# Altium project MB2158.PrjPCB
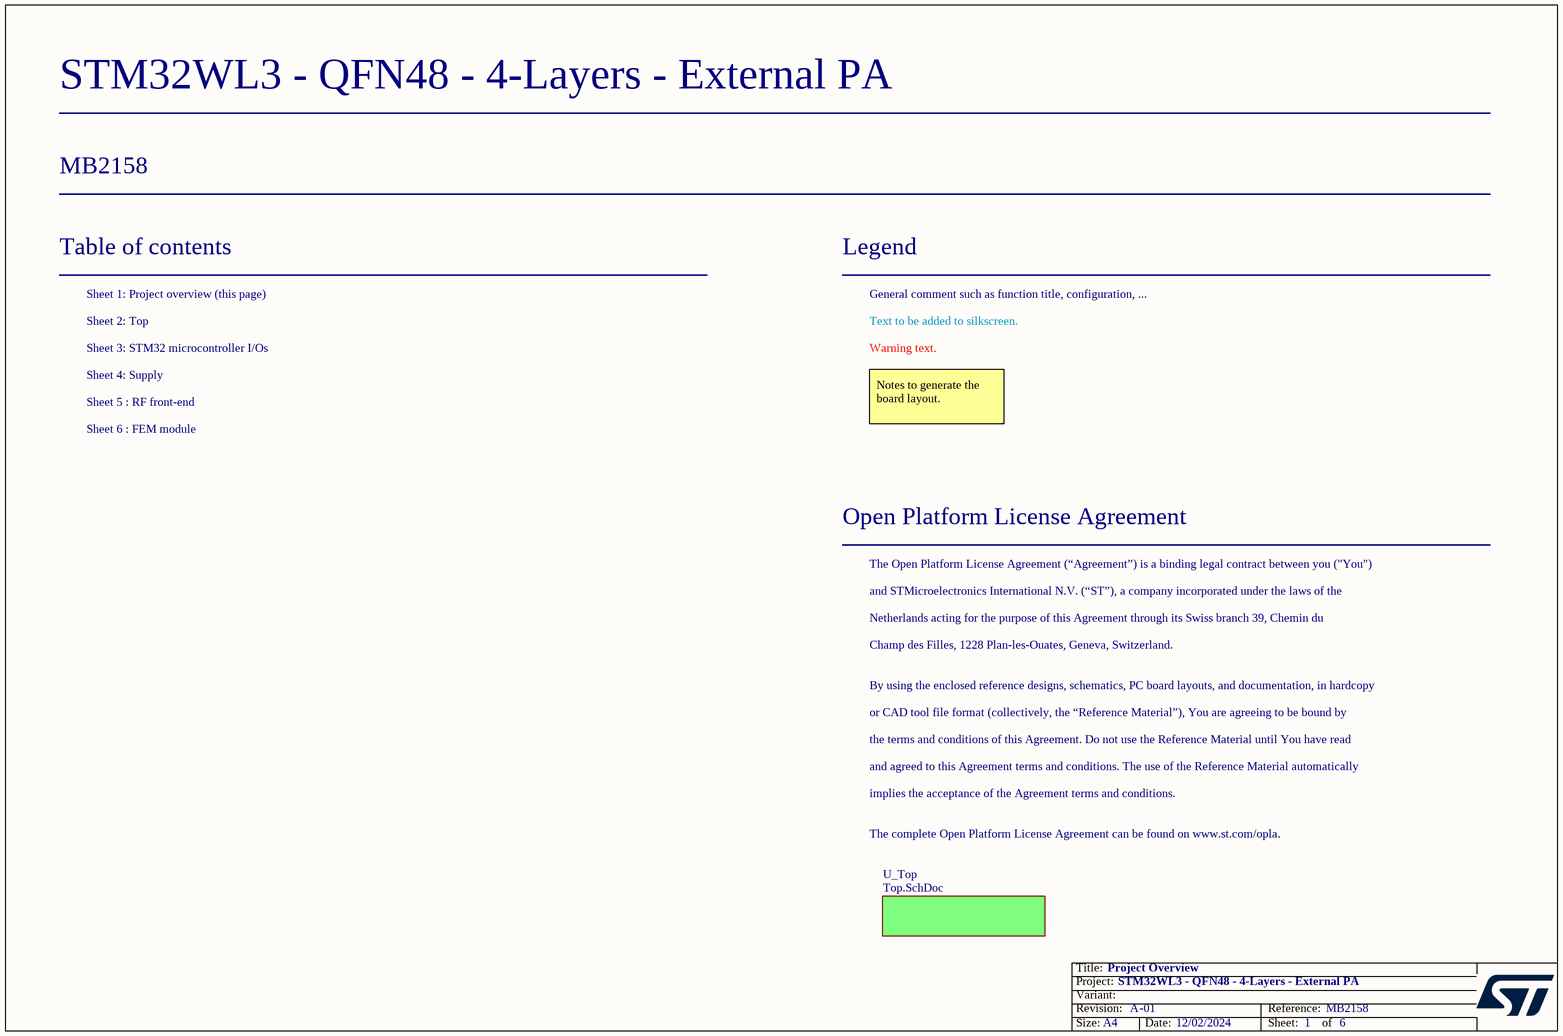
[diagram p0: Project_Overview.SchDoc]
Board_Assembly_Revision: 01; Board_Document_Date: 12/02/2024; Board_Name: STM32WL3 - QFN48 - 4-Layers - External PA; Board_PCB_Revision: A; Board_Reference: MB2158
6 sheets, 108 parts. Net scope: flat (ports and power ports of the same name join across sheets).
Board file: MB2158.PcbDoc
Sheets:
  Project_Overview.SchDoc
    U_Top = Top.SchDoc
      Designator = MCU_IOs.SchDoc
      Designator = RF.SchDoc
      Designator = Supply.SchDoc
      U_FEM = FEM.SchDoc

## Sheet Project_Overview.SchDoc: Project Overview
size A4; Date: Not used; ApprovedBy: Not used; CheckedBy: Not used; Author: Not used; CompanyName: STMicroelectronics; DrawnBy: Not used; Engineer: Not used; Organization: Not used; Address1: Not used; Address2: Not used; Address3: Not used; Address4: Not used; DocumentNumber: Not used; Revision: Not used; SheetNumber: 1; SheetTotal: 6

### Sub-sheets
U_Top = Top.SchDoc: no entries

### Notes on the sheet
- Table of contents
- Sheet 1: Project overview (this page)
- Legend
- General comment such as function title, configuration, ...
- Sheet 2: Top
- Sheet 3: STM32 microcontroller I/Os
- Sheet 4: Supply
- Text to be added to silkscreen.
- Warning text.
- Sheet 5 : RF front-end
- Sheet 6 : FEM module
- Notes to generate the board layout.
- Open Platform License Agreement
- The Open Platform License Agreement (“Agreement”) is a binding legal contract between you ("You")
- and STMicroelectronics International N.V. (“ST”), a company incorporated under the laws of the
- Netherlands acting for the purpose of this Agreement through its Swiss branch 39, Chemin du
- Champ des Filles, 1228 Plan-les-Ouates, Geneva, Switzerland.
- By using the enclosed reference designs, schematics, PC board layouts, and documentation, in hardcopy
- or CAD tool file format (collectively, the “Reference Material”), You are agreeing to be bound by
- the terms and conditions of this Agreement. Do not use the Reference Material until You have read
- and agreed to this Agreement terms and conditions. The use of the Reference Material automatically
- implies the acceptance of the Agreement terms and conditions.
- The complete Open Platform License Agreement can be found on www.st.com/opla.

## Sheet Top.SchDoc: Top Schematic
size A4; Date: Not used; ApprovedBy: Not used; CheckedBy: Not used; Author: Not used; CompanyName: STMicroelectronics; DrawnBy: Not used; Engineer: Not used; Organization: Not used; Address1: Not used; Address2: Not used; Address3: Not used; Address4: Not used; DocumentNumber: Not used; Revision: Not used; SheetNumber: 2; SheetTotal: 6
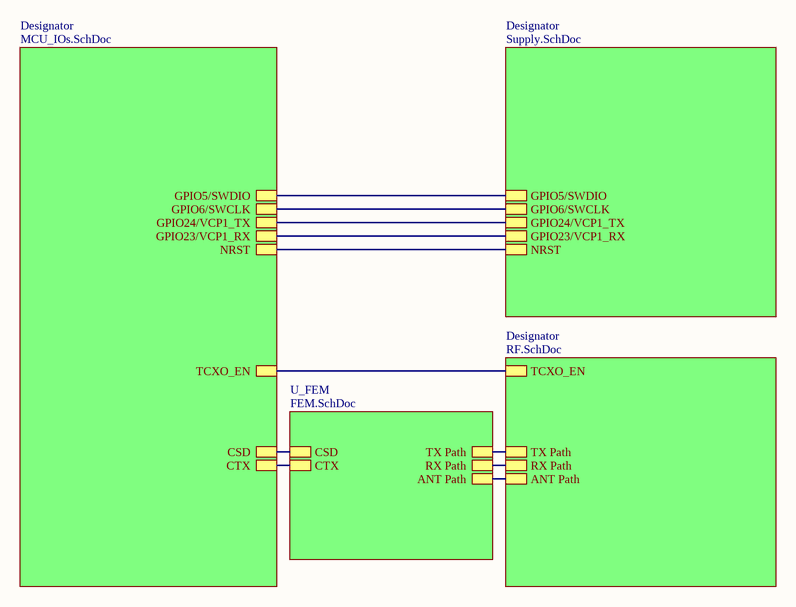
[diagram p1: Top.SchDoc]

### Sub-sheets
Designator = MCU_IOs.SchDoc: NRST, GPIO5/SWDIO, GPIO6/SWCLK, GPIO24/VCP1_TX, GPIO23/VCP1_RX, CTX, CSD, TCXO_EN
Designator = RF.SchDoc: RX Path, TX Path, ANT Path, TCXO_EN
Designator = Supply.SchDoc: NRST, GPIO5/SWDIO, GPIO6/SWCLK, GPIO23/VCP1_RX, GPIO24/VCP1_TX
U_FEM = FEM.SchDoc: TX Path, RX Path, CSD, CTX, ANT Path

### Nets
(unnamed): sheet Designator/NRST, sheet Designator/NRST
(unnamed): sheet Designator/GPIO5/SWDIO, sheet Designator/GPIO5/SWDIO  [a separate net that carries the same name]
(unnamed): sheet Designator/GPIO6/SWCLK, sheet Designator/GPIO6/SWCLK  [a separate net that carries the same name]
(unnamed): sheet Designator/GPIO24/VCP1_TX, sheet Designator/GPIO24/VCP1_TX  [a separate net that carries the same name]
(unnamed): sheet Designator/GPIO23/VCP1_RX, sheet Designator/GPIO23/VCP1_RX  [a separate net that carries the same name]
(unnamed): sheet Designator/CTX, sheet U_FEM/CTX  [a separate net that carries the same name]
(unnamed): sheet Designator/CSD, sheet U_FEM/CSD  [a separate net that carries the same name]
(unnamed): sheet Designator/TCXO_EN, sheet Designator/TCXO_EN  [a separate net that carries the same name]
(unnamed): sheet Designator/RX Path, sheet U_FEM/RX Path  [a separate net that carries the same name]
(unnamed): sheet Designator/TX Path, sheet U_FEM/TX Path  [a separate net that carries the same name]
(unnamed): sheet Designator/ANT Path, sheet U_FEM/ANT Path  [a separate net that carries the same name]

## Sheet MCU_IOs.SchDoc: STM32 I/Os & Clock
size A4; Date: Not used; ApprovedBy: Not used; CheckedBy: Not used; Author: Not used; CompanyName: STMicroelectronics; DrawnBy: Not used; Engineer: Not used; Organization: Not used; Address1: Not used; Address2: Not used; Address3: Not used; Address4: Not used; DocumentNumber: Not used; Revision: Not used; SheetNumber: 3; SheetTotal: 6
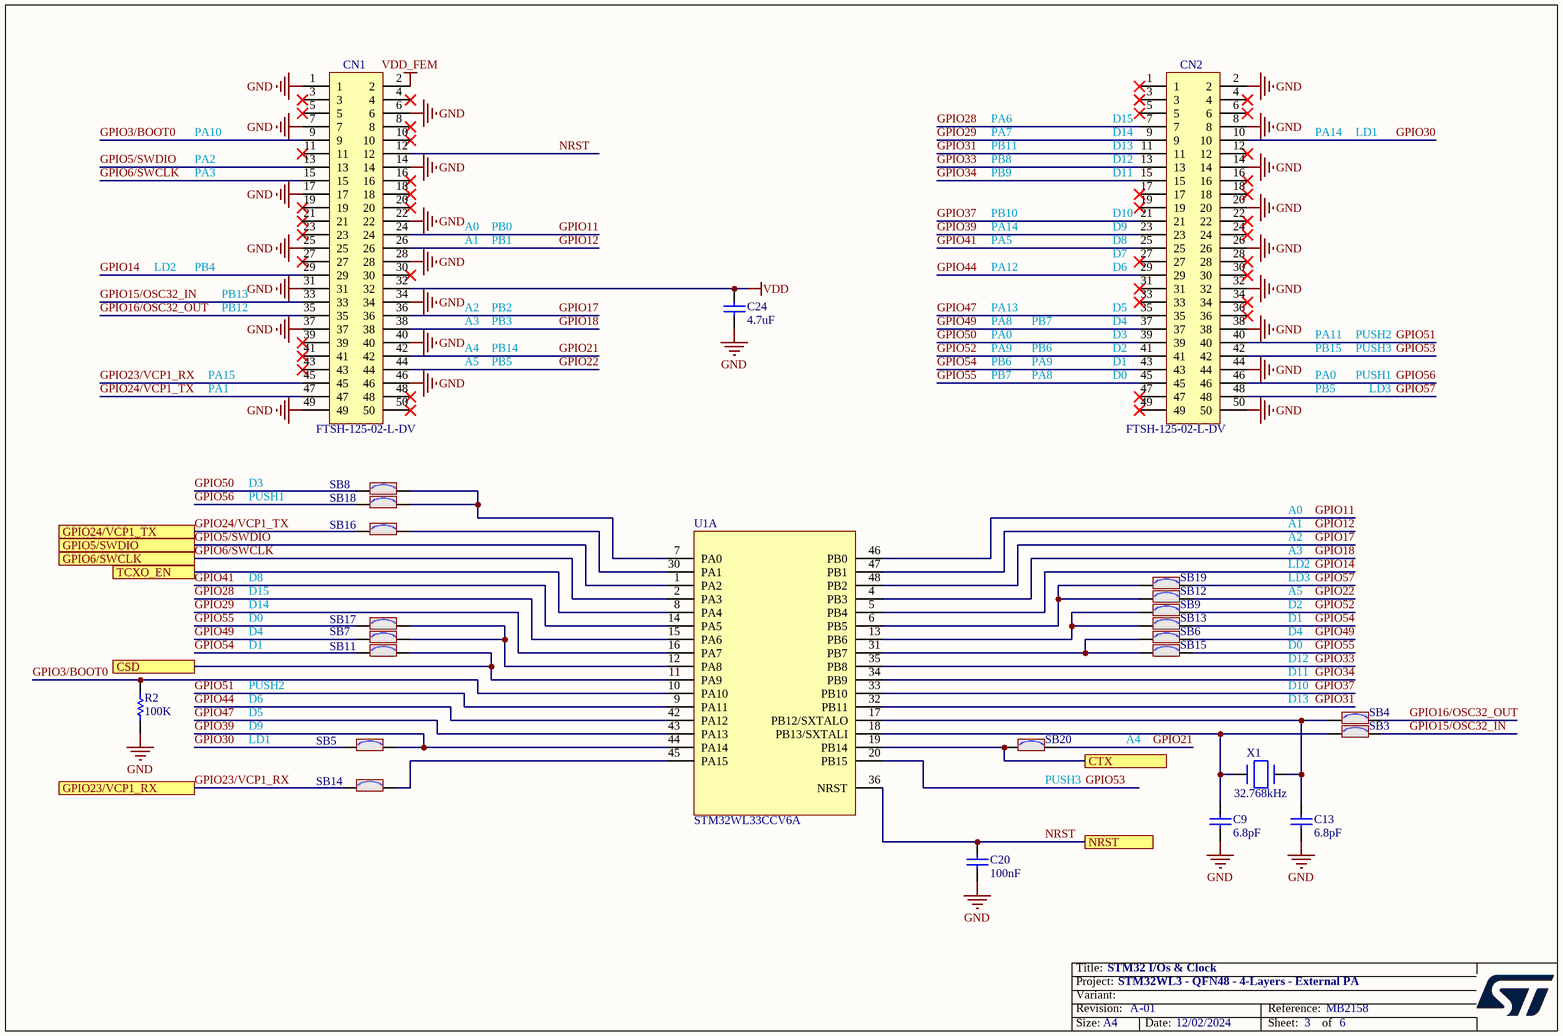
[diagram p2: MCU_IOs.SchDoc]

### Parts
C9  value 6.8pF  [C0402]  (hidden comment: Capacitor)
C13  value 6.8pF  [C0402]  (hidden comment: Capacitor)
C20  value 100nF  [C0402]  (hidden comment: Capacitor)
C24  value 4.7uF  [C0402]  (hidden comment: Capacitor)
CN1  FTSH-125-02-L-DV  [CON_SAMTEC_FTSH-125-02-L-DV]
CN2  FTSH-125-02-L-DV  [CON_SAMTEC_FTSH-125-02-L-DV]
R2  value 100K  [R0402]  (hidden comment: Resistor)
SB3  SB_ON  [SOLDER-BRIDGE_R0402-0R]  (value not drawn)
SB4  SB_ON  [SOLDER-BRIDGE_R0402-0R]  (value not drawn)
SB5  SB_ON  [SOLDER-BRIDGE_R0402-0R]  (value not drawn)
SB6  SB_ON  [SOLDER-BRIDGE_R0402-0R]  (value not drawn)
SB7  SB_ON  [SOLDER-BRIDGE_R0402-0R]  (value not drawn)
SB8  SB_ON  [SOLDER-BRIDGE_R0402-0R]  (value not drawn)
SB9  SB_ON  [SOLDER-BRIDGE_R0402-0R]  (value not drawn)
SB11  SB_ON  [SOLDER-BRIDGE_R0402-0R]  (value not drawn)
SB12  SB_ON  [SOLDER-BRIDGE_R0402-0R]  (value not drawn)
SB13  SB_ON  [SOLDER-BRIDGE_R0402-0R]  (value not drawn)
SB14  SB_ON  [SOLDER-BRIDGE_R0402-0R]  (value not drawn)
SB15  SB_ON  [SOLDER-BRIDGE_R0402-0R]  (value not drawn)
SB16  SB_ON  [SOLDER-BRIDGE_R0402-0R]  (value not drawn)
SB17  SB_ON  [SOLDER-BRIDGE_R0402-0R]  (value not drawn)
SB18  SB_ON  [SOLDER-BRIDGE_R0402-0R]  (value not drawn)
SB19  SB_ON  [SOLDER-BRIDGE_R0402-0R]  (value not drawn)
SB20  SB_ON  [SOLDER-BRIDGE_R0402-0R]  (value not drawn)
U1  value STM32WL33CCV6A  [ICC_QFN48-EPAD-4P5X4P5_6X6_P040]  (hidden comment: STM32WL33)  (part A of 3)
X1  value 32.768kHz  [CRY_NX2012SA_2P]  (hidden comment: XTAL_2_PINS)

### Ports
CSD, CTX, GPIO5/SWDIO, GPIO6/SWCLK, GPIO23/VCP1_RX, GPIO24/VCP1_TX, NRST, TCXO_EN

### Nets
GND: C9.1 C13.1 C20.1 C24.1 CN1.1 CN1.6 CN1.7 CN1.14 CN1.17 CN1.22 CN1.25 CN1.28 CN1.31 CN1.34 CN1.37 CN1.40 CN1.46 CN1.49 CN2.2 CN2.8 CN2.14 CN2.20 CN2.26 CN2.32 CN2.38 CN2.44 CN2.50 R2.1
VDD: C24.2 CN1.32
VDD_FEM: CN1.2
CSD: SB11.2 U1.11(PA9) ; port CSD
CTX: SB20.1 U1.19(PB14) ; port CTX
GPIO3/BOOT0: CN1.9 R2.2 U1.10(PA10)
GPIO5/SWDIO: CN1.13 U1.1(PA2) ; port GPIO5/SWDIO
GPIO6/SWCLK: CN1.15 U1.2(PA3) ; port GPIO6/SWCLK
GPIO11: CN1.24 U1.46(PB0)
GPIO12: CN1.26 U1.47(PB1)
GPIO14: CN1.29 U1.5(PB4)
GPIO15/OSC32_IN: CN1.33 SB3.2
GPIO16/OSC32_OUT: CN1.35 SB4.2
GPIO17: CN1.36 U1.48(PB2)
GPIO18: CN1.38 U1.4(PB3)
GPIO21: CN1.42 SB20.2
GPIO22: CN1.44 SB12.2
GPIO23/VCP1_RX: CN1.45 SB14.1 ; port GPIO23/VCP1_RX
GPIO24/VCP1_TX: CN1.47 SB16.1 ; port GPIO24/VCP1_TX
GPIO28: CN2.7 U1.15(PA6)
GPIO29: CN2.9 U1.16(PA7)
GPIO30: CN2.10 SB5.1
GPIO31: CN2.11 U1.32(PB11)
GPIO33: CN2.13 U1.35(PB8)
GPIO34: CN2.15 U1.34(PB9)
GPIO37: CN2.21 U1.33(PB10)
GPIO39: CN2.23 SB5.2 U1.44(PA14)
GPIO41: CN2.25 U1.14(PA5)
GPIO44: CN2.29 U1.42(PA12)
GPIO47: CN2.35 U1.43(PA13)
GPIO49: CN2.37 SB6.2 SB7.1
GPIO50: CN2.39 SB8.1
GPIO51: CN2.40 U1.9(PA11)
GPIO52: CN2.41 SB9.2
GPIO53: CN2.42 U1.20(PB15)
GPIO54: CN2.43 SB11.1 SB13.2
GPIO55: CN2.45 SB15.2 SB17.1
GPIO56: CN2.46 SB18.1
GPIO57: CN2.48 SB19.2
NRST: C20.2 CN1.12 U1.36(NRST) ; port NRST
TCXO_EN: U1.8(PA4) ; port TCXO_EN
NetC9_2: C9.2 SB3.1 U1.18(PB13/SXTALI) X1.2(X2)
NetC13_2: C13.2 SB4.1 U1.17(PB12/SXTALO) X1.1(X1)
NetSB6_1: SB6.1 SB15.1 U1.31(PB7)
NetSB7_2: SB7.2 SB17.2 U1.12(PA8)
NetSB8_2: SB8.2 SB18.2 U1.7(PA0)
NetSB9_1: SB9.1 SB13.1 U1.13(PB6)
NetSB12_1: SB12.1 SB19.1 U1.6(PB5)
NetSB14_2: SB14.2 U1.45(PA15)
NetSB16_2: SB16.2 U1.30(PA1)

Not connected (* = marked no-connect by the designer): CN1 3* 4* 5* 8* 10* 11* 16* 18* 19* 20* 21* 23* 27* 30* 39* 41* 43* 48* 50*; CN2 1* 3* 4* 5* 6* 12* 16* 17* 18* 19* 22* 24* 27* 28* 30* 31* 33* 34* 36* 47* 49*

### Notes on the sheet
- PA10
- PA2
- PA3
- PA7
- PA6
- PB8
- PB11
- PB9
- (near CN2) D11
- (near CN2) D13
- (near CN2) D14
- (near CN2) D15
- (near CN2) D12
- PA14
- LD1
- A0
- A1
- PB1
- PB0
- PA5
- PB10
- (near CN2) D10
- (near CN2) D9
- (near CN2) D8
- LD2
- PB4
- PB13
- PB12
- A2
- PB2
- PA13
- PA12
- (near CN2) D7
- (near CN2) D6
- (near CN2) D5
- PA15
- A5
- A4
- A3
- PB5
- PB14
- PB3
- PB7
- PB6
- PA0
- PA9
- PA8
- (near CN2) D1
- (near CN2) D4
- (near CN2) D3
- (near CN2) D2
- (near CN2) D0
- PA11
- PB15
- PUSH1
- PUSH2
- PUSH3
- PA1
- LD3
- D3
- D8
- D14
- D15
- D1
- D0
- D4
- D2
- D6
- D5
- D10
- D12
- D11
- D13
- D9
- (near SB20) PUSH3

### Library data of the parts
C9 C13 = MCD-03452: Capacitor, MLCC, 6.8pF, ±0.05pF, C0G, 50V, 0402, T=0.5mm; Part_Preference: Recommended; Manufacturer: MURATA; Manufacturer_Part_Number: GJM1555C1H6R8WB01; Order_Code_RS: NA; ShowFields: YES; ID: 5568
C20 = MCD-00006: Capacitor, MLCC, 100nF, 16V, X7R, +/-10%, 0402, T=0.5mm; Manufacturer_Part_Number: CC0402KRX7R7BB104; Manufacturer: YAGEO; Alternate_Manufacturer_Part_Number: GCM155R71C104KA55D; Alternate_Manufacturer: MURATA; Part_Preference: Recommended; Order_Code_RS: 616-9701
C24 = MCD-03431: Capacitor, MLCC, 4.7uF, X5R, 10 V, 0402, ± 20%, T=0.5mm; Part_Preference: Recommended; Manufacturer: MURATA; Manufacturer_Part_Number: GRM155R61A475MEAAD; Order_Code_RS: 172-6870; ShowFields: YES; ID: 5547
CN1 CN2 = MCD-02746: Header, 25x2, 12.7mm, VR, SMD, T=4.83mm; Part_Type: Connector; Part_Preference: Recommended; Manufacturer: SAMTEC; Value: Header 25x2; ShowFields: YES; ID: 4858; Component_Country_Of_Origin: China, Costa Rica, Malaysia, USA, Vietnam
R2 = MCD-03301: Resistor, 100K, 0402, +/-1%, 1/16W; Part_Preference: Alternate; Manufacturer: YAGEO; Manufacturer_Part_Number: RT0402FRE07100KL; Alternate_EMS: M; ShowFields: YES; ID: 5417
SB3-SB9 SB11-SB20 = MCD-01618: Solder Bridge 0402 ON; Part_Type: Misc; Part_Preference: Recommended; Manufacturer: YAGEO; Manufacturer_Part_Number: RC0402JR-070RL; Order_Code_RS: 618-5804; Component_Country_Of_Origin: China
U1 = MCD-03488: IC, Programmable Sub-1GHz wireless SoC; Part_Preference: Recommended; Manufacturer: STMICROELECTRONICS; Component_Country_Of_Origin: Unknown; ShowFields: YES; ID: 5604
X1 = MCD-01445: Crystal, 32.768kHz, 7pF, +/-20ppm, 80K, 2.05x1.2mm; BMS_Part_Number: 9157043; Part_Type: Crystal_Osc; Part_Preference: Recommended; Manufacturer: NDK; Manufacturer_Part_Number: NX2012SA-32.768KHZ-EXS00A-MU00389; Component_Country_Of_Origin: Unknown; ShowFields: YES; ID: 3545

## Sheet RF.SchDoc: STM32 RF
size A4; Date: Not used; ApprovedBy: Not used; CheckedBy: Not used; Author: Not used; CompanyName: STMicroelectronics; DrawnBy: Not used; Engineer: Not used; Organization: Not used; Address1: Not used; Address2: Not used; Address3: Not used; Address4: Not used; DocumentNumber: Not used; Revision: Not used; SheetNumber: 5; SheetTotal: 6
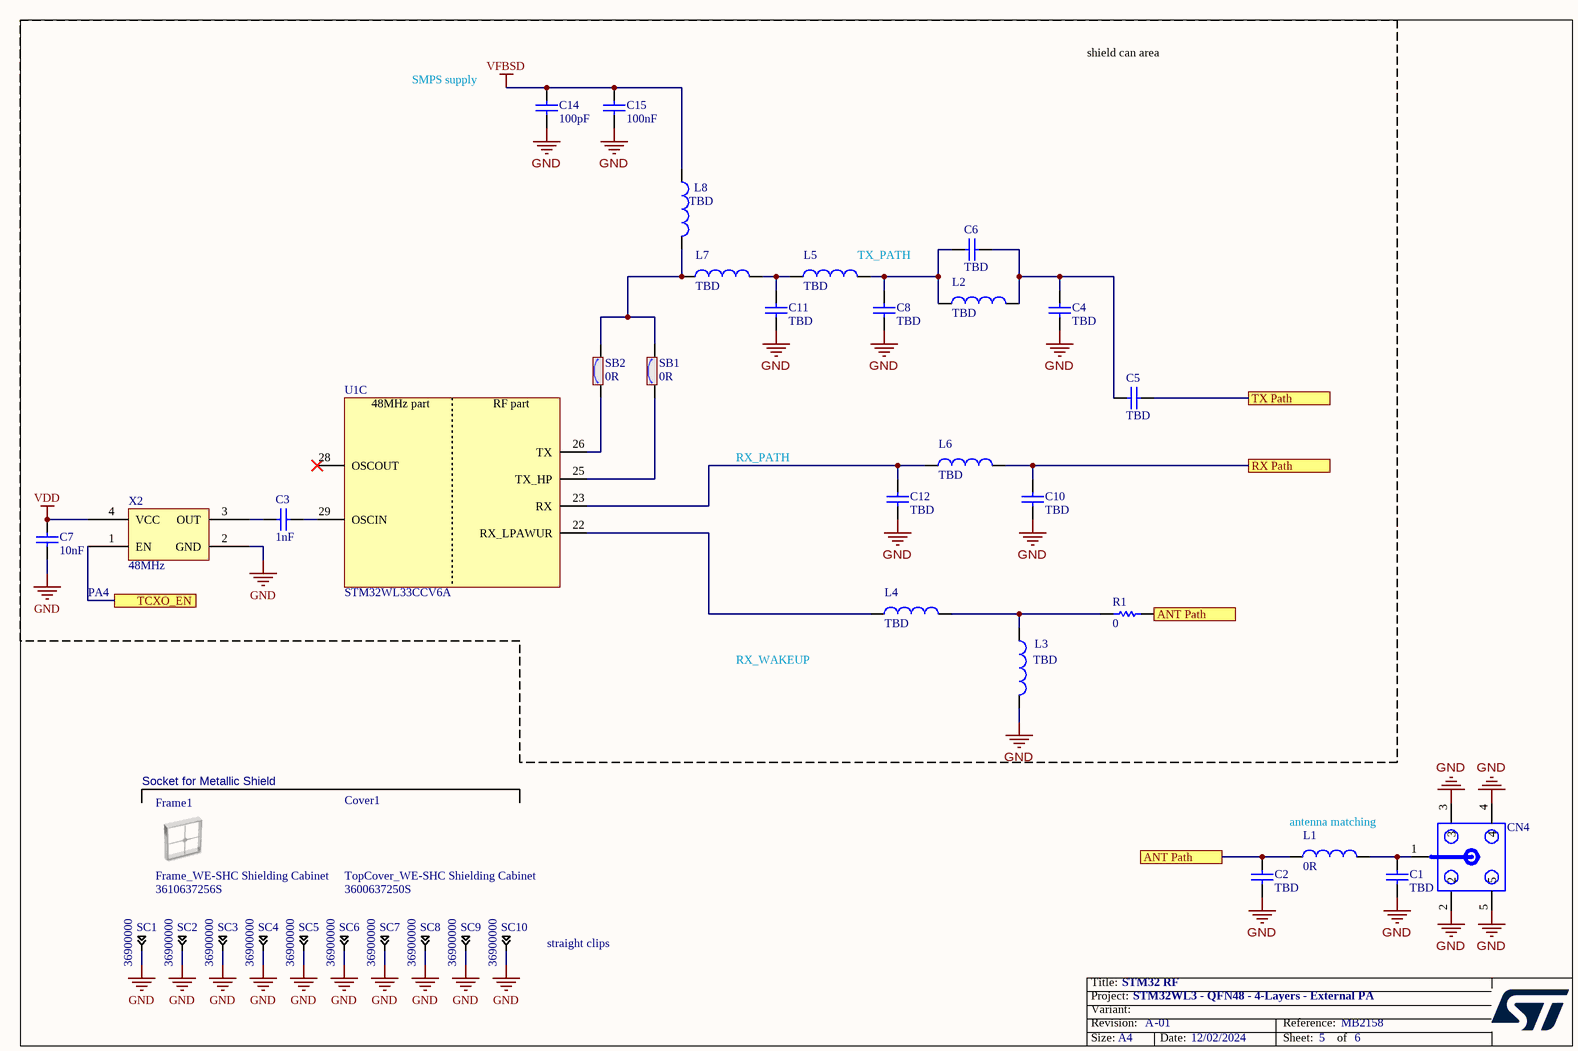
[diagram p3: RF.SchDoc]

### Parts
C1  value TBD  [C0402]  (hidden comment: Capacitor)
C2  value TBD  [C0402]  (hidden comment: Capacitor)
C3  value 1nF  [C0402]  (hidden comment: Capacitor)
C4  value TBD  [C0402]  (hidden comment: Capacitor)
C5  value TBD  [C0402]  (hidden comment: Capacitor)
C6  value TBD  [C0402]  (hidden comment: Capacitor)
C7  value 10nF  [C0402]  (hidden comment: Capacitor)
C8  value TBD  [C0402]  (hidden comment: Capacitor)
C10  value TBD  [C0402]  (hidden comment: Capacitor)
C11  value TBD  [C0402]  (hidden comment: Capacitor)
C12  value TBD  [C0402]  (hidden comment: Capacitor)
C14  value 100pF  [C0402]  (hidden comment: Capacitor)
C15  value 100nF  [C0402]  (hidden comment: Capacitor)
CN4  mmcx  [CON_SMA-RF_CINCH_142-0701-851]  (value not drawn)
Cover1  TopCover_WE-SHC Shielding Cabinet  value 3600637250S  [3600637250S]
Frame1  Frame_WE-SHC Shielding Cabinet  value 3610637256S  [3610637256S]
L1  value 0R  [L0402]  (hidden comment: Inductor)
L2  value TBD  [L0402]  (hidden comment: Inductor)
L3  value TBD  [L0402]  (hidden comment: Inductor)
L4  value TBD  [L0402]  (hidden comment: Inductor)
L5  value TBD  [L0402]  (hidden comment: Inductor)
L6  value TBD  [L0402]  (hidden comment: Inductor)
L7  value TBD  [L0402]  (hidden comment: Inductor)
L8  value TBD  [L0402]  (hidden comment: Inductor)
R1  value 0  [GRM155--GJM155-0_05-MFG]  (hidden comment: Resistor)
SB1  value 0R  [SOLDER-BRIDGE_R0201_0R]  (hidden comment: SB_ON)
SB2  value 0R  [SOLDER-BRIDGE_R0201_0R]  (hidden comment: SB_ON)
SC1  value 36900000  [3690000]  (hidden comment: Shield-clip)
SC2  value 36900000  [3690000]  (hidden comment: Shield-clip)
SC3  value 36900000  [3690000]  (hidden comment: Shield-clip)
SC4  value 36900000  [3690000]  (hidden comment: Shield-clip)
SC5  value 36900000  [3690000]  (hidden comment: Shield-clip)
SC6  value 36900000  [3690000]  (hidden comment: Shield-clip)
SC7  value 36900000  [3690000]  (hidden comment: Shield-clip)
SC8  value 36900000  [3690000]  (hidden comment: Shield-clip)
SC9  value 36900000  [3690000]  (hidden comment: Shield-clip)
SC10  value 36900000  [3690000]  (hidden comment: Shield-clip)
U1  value STM32WL33CCV6A  [ICC_QFN48-EPAD-4P5X4P5_6X6_P040]  (hidden comment: STM32WL33)  (part C of 3)
X2  48MHz  [NT2016SJA]

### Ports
ANT Path, RX Path, TCXO_EN, TX Path

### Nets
GND: C1.1 C2.1 C4.1 C7.1 C8.1 C10.1 C11.1 C12.1 C14.2 C15.1 CN4.2 CN4.3 CN4.4 CN4.5 L3.2 SC1.1 SC2.1 SC3.1 SC4.1 SC5.1 SC6.1 SC7.1 SC8.1 SC9.1 SC10.1 X2.2(GND)
VDD: C7.2 X2.4(VCC)
VFBSD: C14.1 C15.2 L8.1
ANT Path: C2.2 L1.1 R1.1 ; port ANT Path
RX Path: C10.2 L6.2 ; port RX Path
TCXO_EN: X2.1(EN) ; port TCXO_EN
TX Path: C5.1 ; port TX Path
NetC1_2: C1.2 CN4.1 L1.2
NetC3_1: C3.1 U1.29(OSCIN)
NetC3_2: C3.2 X2.3(OUT)
NetC4_2: C4.2 C5.2 C6.2 L2.2
NetC6_1: C6.1 C8.2 L2.1 L5.2
NetC11_2: C11.2 L5.1 L7.2
NetC12_2: C12.2 L6.1 U1.23(RX)
NetL3_1: L3.1 L4.2 R1.2
NetL4_1: L4.1 U1.22(RX_LPAWUR)
NetL7_1: L7.1 L8.2 SB1.2 SB2.2
NetSB1_1: SB1.1 U1.25(TX_HP)
NetSB2_1: SB2.1 U1.26(TX)

Not connected (* = marked no-connect by the designer): U1 28(OSCOUT)*

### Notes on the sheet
- shield can area
- SMPS supply
- (near L5) TX_PATH
- RX_PATH
- PA4
- RX_WAKEUP
- Socket for Metallic Shield
- antenna matching
- (near SC10) straight clips

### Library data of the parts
C1 C2 = MCD-01600: Capacitor, MLCC, 1pF, 50V, NPO, +/-0.1pF, 0402, T=0.5mm; Part_Preference: Recommended; Manufacturer: YAGEO; Component_Country_Of_Origin: China; ShowFields: YES; ID: 3700
C3 = MCD-03555: Capacitor, MLCC, 1nF, 50V, C0G, +/-0.1pF, 0402, T=0.5mm; Part_Preference: Recommended; Manufacturer: MURATA; Manufacturer_Part_Number: GRM1555C1H102JA01; ShowFields: YES; ID: 5671
C4 = MCD-03448: Capacitor, MLCC, 2.7pF, 50V, C0G, +/-0.05pF, C0G, 0402, T=0.5mm; Part_Preference: Recommended; Manufacturer: MURATA; ShowFields: YES; ID: 5564
C5 = MCD-03446: Capacitor, MLCC, 100pF, 50V, COG, 1%, 0402, T=0.5mm; Part_Preference: Recommended; Manufacturer: MURATA; Order_Code_RS: 247-7780; ShowFields: YES; ID: 5562
C6 = MCD-02065: Capacitor, Monolithic CC, 1.2pF, 50V, +/-0.05pf, 0402, T=0.5mm; Part_Preference: Recommended; Manufacturer: MURATA; Order_Code_RS: 846-7246; Component_Country_Of_Origin: Japan; ShowFields: YES; ID: 4165
C7 = MCD-03555: Capacitor, MLCC, 10nF, 50V, COG, +/-1%, 0402, T=0.5mm; Part_Preference: Recommended; Manufacturer: MURATA; Manufacturer_Part_Number: GRM1555C1E103JE01; ShowFields: YES; ID: 5671
C8 = MCD-01374: Capacitor, MLCC, 5.6pF, 50V, NPO, +/-0.1pF, 0402, T=0.5mm; Part_Preference: Recommended; Manufacturer: YAGEO; Component_Country_Of_Origin: China; ShowFields: YES; ID: 3474
C10 = MCD-02994: Capacitor, MLCC, 1.5pF, 50V, C0G, +/-0.25pF, 0402, T=0.5mm; Part_Preference: Recommended; Manufacturer: MURATA; Component_Country_Of_Origin: Japan°; ShowFields: YES; ID: 5110
C11 = MCD-03555: Capacitor, MLCC, 5.3pF, 50V, C0G, +/-0.1pF, 0402, T=0.5mm; Part_Preference: Recommended; Manufacturer: MURATA; ShowFields: YES; ID: 5671
C12 = MCD-02215: Capacitor, MLCC, 0.5pF, 50V, C0G, +/-0.1pF, 0402, T=0.5mm; Part_Preference: Recommended; Manufacturer: MURATA; Order_Code_RS: 723-5111P; Component_Country_Of_Origin: Japan; ShowFields: YES; ID: 4315
C14 = MCD-03446: Capacitor, MLCC, 100pF, 50V, COG, 1%, 0402, T=0.5mm; Part_Preference: Recommended; Manufacturer: MURATA; Manufacturer_Part_Number: GCM1555C1H101FA16; Order_Code_RS: 247-7780; ShowFields: YES; ID: 5562
C15 = MCD-03442: Capacitor, MLCC, 100nF, +/-10%, X7R, 25V, 0402, T=0.5mm; Part_Preference: Recommended; Manufacturer: MURATA; Manufacturer_Part_Number: GRM155R71E104KE14D; Order_Code_RS: 247-8011; ShowFields: YES; ID: 5558
CN4 = MCD-02072: Jack_SMA, VR, PCB edge, 50R, T=7.92mm; Part_Type: Connector; Part_Preference: Recommended; Manufacturer: CINCH; Manufacturer_Part_Number: 142-0701-851; Order_Code_RS: 885-7532; Component_Country_Of_Origin: United States; ShowFields: YES; ID: 4172
Cover1 = TopCover_WE-SHC Shielding Cabinet: two-piece frame 37.7*25*5.8 mm; Manufacturer: Wurth Elektronik
Frame1 = Frame_WE-SHC Shielding Cabinet: two-piece frame 37.7*25*5.8 mm; Manufacturer: Wurth Elektronik
L1 = MCD-01937: Resistor, 0R, 0402, +/-5%, 1/16W; Part_Preference: Recommended; Manufacturer: YAGEO; Manufacturer_Part_Number: RC0402JR-070RL; Order_Code_RS: 618-5804; Component_Country_Of_Origin: China; ShowFields: YES; ID: 4037
L2 = MCD-03460: Inductor, Wire-wound, 5.6nH, ±0.1nH, 1770mA, 40mR, 0402, T=0.5mm; Part_Preference: Recommended; Manufacturer: MURATA; Order_Code_RS: NA; ShowFields: YES; ID: 5576
L3 = MCD-03462: Inductor, MLCC, 5.6nH, ±0.3nH, 650mA, 180mR, 0402, T=0.5mm; Part_Preference: Recommended; Manufacturer: MURATA; Order_Code_RS: 124-8165; ShowFields: YES; ID: 5578
L4 = MCD-03461: Inductor, 6.8nH, +/-3%, 0.6A, 220mR, 0402, T=0.5mm
L5 = MCD-03459: Inductor, Wire-wound, 6.2nH, ±0.1nH, 1600mA, 56mR, 0402, T=0.5mm; Part_Preference: Recommended; Manufacturer: MURATA; Order_Code_RS: NA; ShowFields: YES; ID: 5575
L6 = MCD-01766: Inductor, 15nH, +/-2%, Itemp=460mA max, 0R16, 0402, T= 0.6mm, Qmin=30
L7 = MCD-03457: Inductor, Wire-wound, 3.6nH, ±0.1nH, 1950mA, 30mR, 0402, T=0.5mm; Part_Preference: Recommended; Manufacturer: MURATA; Order_Code_RS: 166-9582; ShowFields: YES; ID: 5573
L8 = MCD-03456: Inductor, Wire-wound, 12nHH, ±2%, 500mA, 1405mR, 0402, T=0.5mm; Part_Preference: Recommended; Manufacturer: MURATA; Order_Code_RS: 167-4829; ShowFields: YES; ID: 5572
R1 = MCD-03301: 0 ohm resistor; Part_Preference: Alternate; Manufacturer: YAGEO; Manufacturer_Part_Number: RC0402JR-070RL; Alternate_EMS: M; ShowFields: YES; ID: 5417
SB1 SB2 = MCD-03219: Resistor, 0R, 0201, Solder Bridge ON , 1/20W,; Part_Type: Misc; Part_Preference: Recommended; Manufacturer: YAGEO; Manufacturer_Part_Number: RC0201JR-070RL; Order_Code_RS: 198-7623; Component_Country_Of_Origin: China; ShowFields: YES; ID: 5335
SC1-SC10 = Wurth Clip: shield clip Wurth Elektronik  to fix RF shielded cavity; Part_Preference: Recommended
U1 = MCD-03488: as U1 on sheet MCU_IOs
X2 = NT2016SJA: TCXO 48 MHz  NDK Spec. No.:END6296A; Manufacturer_Part_Number: NT2016SJA-END6296A

## Sheet Supply.SchDoc: STM32 power
size A4; Date: Not used; ApprovedBy: Not used; CheckedBy: Not used; Author: Not used; CompanyName: STMicroelectronics; DrawnBy: Not used; Engineer: Not used; Organization: Not used; Address1: Not used; Address2: Not used; Address3: Not used; Address4: Not used; DocumentNumber: Not used; Revision: Not used; SheetNumber: 4; SheetTotal: 6
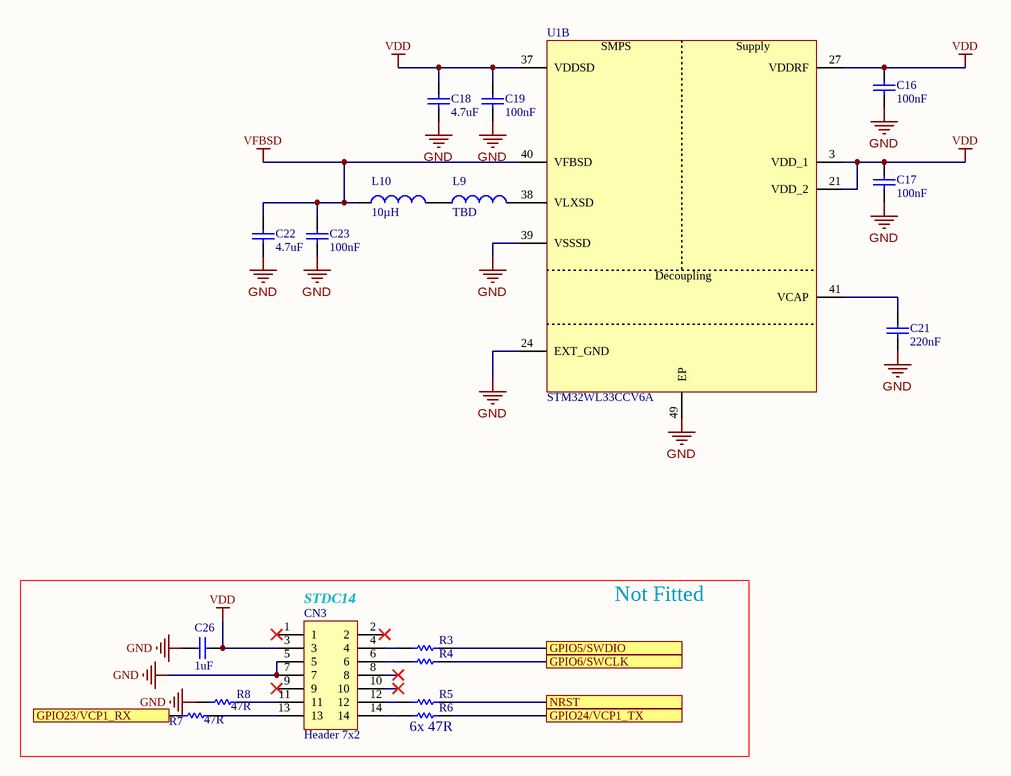
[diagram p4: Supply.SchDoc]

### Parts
C16  value 100nF  [C0402]  (hidden comment: Capacitor)
C17  value 100nF  [C0402]  (hidden comment: Capacitor)
C18  value 4.7uF  [C0402]  (hidden comment: Capacitor)
C19  value 100nF  [C0402]  (hidden comment: Capacitor)
C21  value 220nF  [C0402]  (hidden comment: Capacitor)
C22  value 4.7uF  [C0402]  (hidden comment: Capacitor)
C23  value 100nF  [C0402]  (hidden comment: Capacitor)
C26  value 1uF  [C0603]  (hidden comment: Capacitor)
CN3  Header 7x2  [CON_SAMTEC_FTSH-107-01-L-DV-K-A]
L9  value TBD  [L0402]  (hidden comment: Inductor)
L10  value 10µH  [LQM21FN_70-IPC_C]  (hidden comment: Inductor)
R3  Resistor  [R0402]  (value not drawn)
R4  Resistor  [R0402]  (value not drawn)
R5  Resistor  [R0402]  (value not drawn)
R6  Resistor  [R0402]  (value not drawn)
R7  value 47R  [R0402]  (hidden comment: Resistor)
R8  value 47R  [R0402]  (hidden comment: Resistor)
U1  value STM32WL33CCV6A  [ICC_QFN48-EPAD-4P5X4P5_6X6_P040]  (hidden comment: STM32WL33)  (part B of 3)

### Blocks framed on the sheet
Not Fitted: C26 CN3 R3-R8

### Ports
GPIO5/SWDIO, GPIO6/SWCLK, GPIO23/VCP1_RX, GPIO24/VCP1_TX, NRST

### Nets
GND: C16.1 C17.1 C18.1 C19.1 C21.1 C22.1 C23.2 C26.1 CN3.5 CN3.7 R8.1 U1.24(EXT_GND) U1.39(VSSSD) U1.49(EP)
VDD: C16.2 C17.2 C18.2 C19.2 C26.2 CN3.3 U1.3(VDD_1) U1.21(VDD_2) U1.27(VDDRF) U1.37(VDDSD)
VFBSD: C22.2 C23.1 L10.1 U1.40(VFBSD)
GPIO5/SWDIO: R3.2 ; port GPIO5/SWDIO
GPIO6/SWCLK: R4.2 ; port GPIO6/SWCLK
GPIO23/VCP1_RX: R7.1 ; port GPIO23/VCP1_RX
GPIO24/VCP1_TX: R6.2 ; port GPIO24/VCP1_TX
NRST: R5.2 ; port NRST
NetC21_2: C21.2 U1.41(VCAP)
NetCN3_4: CN3.4 R3.1
NetCN3_6: CN3.6 R4.1
NetCN3_11: CN3.11 R8.2
NetCN3_12: CN3.12 R5.1
NetCN3_13: CN3.13 R7.2
NetCN3_14: CN3.14 R6.1
NetL9_1: L9.1 L10.2
NetL9_2: L9.2 U1.38(VLXSD)

Not connected (* = marked no-connect by the designer): CN3 1* 2* 8* 9* 10*

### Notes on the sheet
- (near CN3) STDC14
- (near R6) 6x 47R

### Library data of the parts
C16 C17 = MCD-03442: Capacitor, MLCC, 100nF, +/-10%, X7R, 25V, 0402, T=0.5mm; Part_Preference: Recommended; Manufacturer: MURATA; Manufacturer_Part_Number: GRM155R71E104KE14D; Order_Code_RS: 247-8011; ShowFields: YES; ID: 5558; Component_Country_Of_Origin: Japan°
C18 C22 = MCD-03431: as C24 on sheet MCU_IOs
C19 C23 = MCD-03442: as C15 on sheet RF
C21 = MCD-03077: Capacitor, MLCC, 220nF, 35V, X6S, +/-10%, 0402, T=0.5mm; Part_Preference: Recommended; Manufacturer: MURATA; Manufacturer_Part_Number: GRM155C8YA224KE01D; Component_Country_Of_Origin: Japan°; ShowFields: YES; ID: 5193
C26 = MCD-00010: Capacitor, MLCC, 1uF, 16V, X5R, 10%, 0603, T=0,8mm; Manufacturer_Part_Number: CC0603KRX5R7BB105; Manufacturer: YAGEO; Provided_By: Subcon; Initial_Board_Reference: MB1274
CN3 = MCD-01531: Header, 7x2, 1.27mm, VR, T=5.97mm, FTSH series STDC14 without Alignment Pin; Part_Type: Connector; Part_Preference: Recommended; Manufacturer: SAMTEC; Manufacturer_Part_Number: FTSH-107-01-L-DV-K; Order_Code_RS: 179-9021; Component_Country_Of_Origin: China, Costa Rica, Malaysia, United States, Vietnam
L9 = MCD-03453: Part_Preference: Recommended; Manufacturer: MURATA; Order_Code_RS: 166-9735; ShowFields: YES; ID: 5569
L10 = MCD-03557: Inductor, 10uH, +/-20%, 100mA, 1R36, 0805, T=0.8mm; Part_Preference: Recommended; Manufacturer: MURATA; Manufacturer_Part_Number: LQM21FN100M80; ShowFields: YES; ID: 5673
R3-R8 = MCD-00481: Resistor,47R,0402,1%,1/16W; Manufacturer_Part_Number: RC0402FR-0747RL; Manufacturer: YAGEO; Provided_By: Subcon
U1 = MCD-03488: as U1 on sheet MCU_IOs

## Sheet FEM.SchDoc: FEM Module
size A4; Board_Assembly_Revision: 01; Date: Not used; ApprovedBy: Not used; CheckedBy: Not used; Author: Not used; CompanyName: STMicroelectronics; DrawnBy: Not used; Engineer: Not used; Organization: Not used; Address1: Not used; Address2: Not used; Address3: Not used; Address4: Not used; DocumentNumber: Not used; Revision: Not used; SheetNumber: 6; SheetTotal: 6
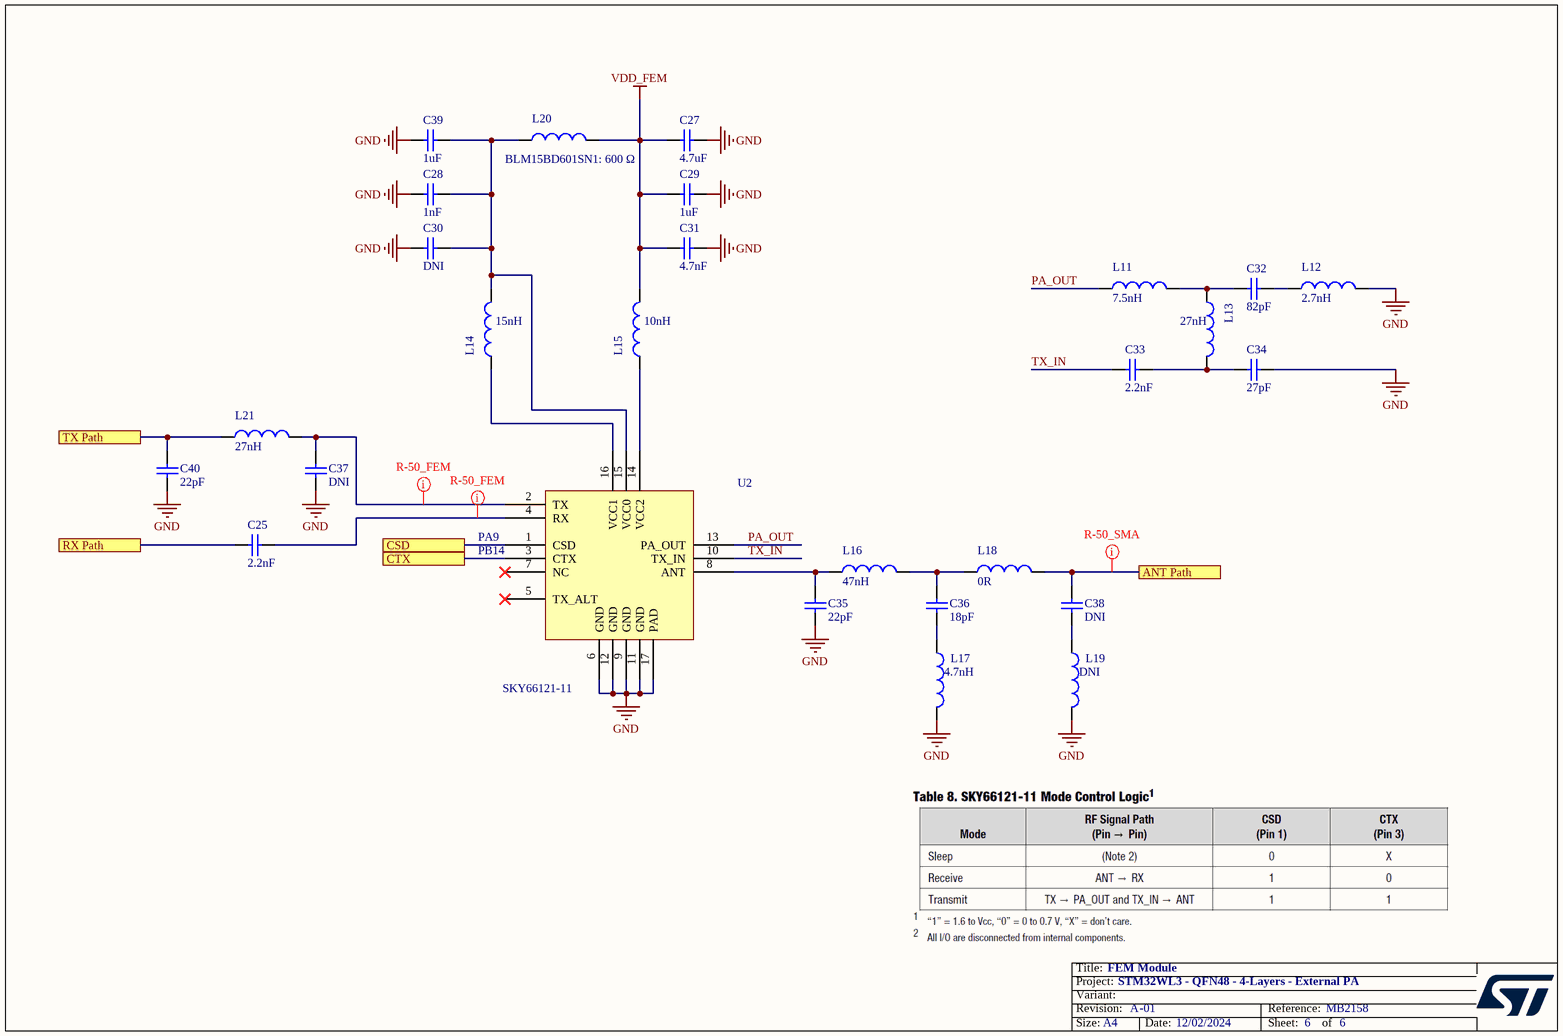
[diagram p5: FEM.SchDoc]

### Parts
C25  value 2.2nF  [C0402]  (hidden comment: Capacitor)
C27  value 4.7uF  [GRM185C80J475ME11D]  (hidden comment: Capacitor)
C28  value 1nF  [C0402]  (hidden comment: Capacitor)
C29  value 1uF  [C0402]  (hidden comment: Capacitor)
C30  value DNI  [C0402]  (hidden comment: Capacitor)
C31  value 4.7nF  [C0402]  (hidden comment: Capacitor)
C32  value 82pF  [C0402]  (hidden comment: Capacitor)
C33  value 2.2nF  [C0402]  (hidden comment: Capacitor)
C34  value 27pF  [C0402]  (hidden comment: Capacitor)
C35  value 22pF  [C0402]  (hidden comment: Capacitor)
C36  value 18pF  [C0402]  (hidden comment: Capacitor)
C37  value DNI  [C0402]  (hidden comment: Capacitor)
C38  value DNI  [C0402]  (hidden comment: Capacitor)
C39  value 1uF  [C0402]  (hidden comment: Capacitor)
C40  value 22pF  [C0402]  (hidden comment: Capacitor)
L11  value 7.5nH  [C0603_coilcraft]  (hidden comment: Inductor)
L12  value 2.7nH  [L0402]  (hidden comment: Inductor)
L13  value 27nH  [C0603_coilcraft]  (hidden comment: Inductor)
L14  value 15nH  [L0402]  (hidden comment: Inductor)
L15  value 10nH  [C0603_coilcraft]  (hidden comment: Inductor)
L16  value 47nH  [C0603_coilcraft]  (hidden comment: Inductor)
L17  value 4.7nH  [L0402]  (hidden comment: Inductor)
L18  value 0R  [C0603_coilcraft]  (hidden comment: Inductor)
L19  value DNI  [L0402]  (hidden comment: Inductor)
L20  BLM15BD601SN1: 600 Ω  [L0402]  (hidden comment: Inductor)
L21  value 27nH  [L0402]  (hidden comment: Inductor)
U2  SKY66121-11  [SKY65367-11]

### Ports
ANT Path, CSD, CTX, RX Path, TX Path

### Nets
GND: C27.2 C28.2 C29.2 C30.2 C31.2 C34.1 C35.1 C37.1 C39.2 C40.1 L12.2 L17.2 L19.2 U2.6(GND) U2.9(GND) U2.11(GND) U2.12(GND) U2.17(PAD)
VDD_FEM: C27.1 C29.1 C31.1 L15.2 L20.2
ANT Path: C38.2 L18.2 ; port ANT Path
CSD: U2.1(CSD) ; port CSD
CTX: U2.3(CTX) ; port CTX
PA_OUT: L11.1 U2.13(PA_OUT)
RX Path: C25.1 ; port RX Path
TX Path: C40.2 L21.1 ; port TX Path
TX_IN: C33.1 U2.10(TX_IN)
NetC25_2: C25.2 U2.4(RX)
NetC28_1: C28.1 C30.1 C39.1 L14.2 L20.1 U2.15(VCC0)
NetC32_1: C32.1 L12.1
NetC32_2: C32.2 L11.2 L13.1
NetC33_2: C33.2 C34.2 L13.2
NetC35_2: C35.2 L16.1 U2.8(ANT)
NetC36_1: C36.1 L17.1
NetC36_2: C36.2 L16.2 L18.1
NetC37_2: C37.2 L21.2 U2.2(TX)
NetC38_1: C38.1 L19.1
NetL14_1: L14.1 U2.16(VCC1)
NetL15_1: L15.1 U2.14(VCC2)

Not connected (* = marked no-connect by the designer): U2 5(TX_ALT)* 7(NC)*

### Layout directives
mark named R-50_FEM: NetC25_2, NetC37_2
mark named R-50_SMA: ANT Path

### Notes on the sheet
- (near U2) PB14
- (near U2) PA9

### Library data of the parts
C25 = MCD-03431: Capacitor, MLCC,  2.2nF, X5R, 10 V, 0402, ± 20%, T=0.5mm; Part_Preference: Recommended; Manufacturer: MURATA; Manufacturer_Part_Number: GRM155R71H222KA01; ShowFields: YES
C27 = MCD-03431: Capacitor, MLCC,  4.7uF, X5R, 10 V, 0402, ± 20%, T=0.5mm; Part_Preference: Recommended; Manufacturer: MURATA; Manufacturer_Part_Number: GRM185C80J475ME11; Order_Code_RS: 172-6870; ShowFields: YES; ID: 5547
C28 = MCD-03431: Capacitor, MLCC,  1nF, X5R, 10 V, 0402, ± 20%, T=0.5mm; Part_Preference: Recommended; Manufacturer: MURATA; Manufacturer_Part_Number: GRM1555C1H102JA01; Order_Code_RS: 172-6870; ShowFields: YES; ID: 5547
C29 C39 = MCD-03431: Capacitor, MLCC,  1uF, X5R, 10 V, 0402, ± 20%, T=0.5mm; Part_Preference: Recommended; Manufacturer: MURATA; Manufacturer_Part_Number: GRT155R60J105KE01; Order_Code_RS: 172-6870; ShowFields: YES; ID: 5547
C30 C38 = MCD-03431: Part_Preference: Recommended; Manufacturer: MURATA; Order_Code_RS: 172-6870; ShowFields: YES; ID: 5547
C31 = MCD-03431: Capacitor, MLCC,  4.7nF, X5R, 10 V, 0402, ± 20%, T=0.5mm; Part_Preference: Recommended; Manufacturer: MURATA; Manufacturer_Part_Number: GRM155R71H472KA01; Order_Code_RS: 172-6870; ShowFields: YES; ID: 5547
C32 = MCD-03431: Capacitor, MLCC,  82pF, X5R, 10 V, 0402, ± 20%, T=0.5mm; Part_Preference: Recommended; Manufacturer: MURATA; Manufacturer_Part_Number: GCM1555C1H820JA16; Order_Code_RS: 172-6870; ShowFields: YES; ID: 5547
C33 = MCD-03431: Capacitor, MLCC,  2.2nF, X5R, 10 V, 0402, ± 20%, T=0.5mm; Part_Preference: Recommended; Manufacturer: MURATA; Manufacturer_Part_Number: GRM155R71H222KA01; Order_Code_RS: 172-6870; ShowFields: YES; ID: 5547
C34 = MCD-03431: Capacitor, MLCC,  27pF, X5R, 10 V, 0402, ± 20%, T=0.5mm; Part_Preference: Recommended; Manufacturer: MURATA; Manufacturer_Part_Number: GJM1555C1H270JB01; Order_Code_RS: 172-6870; ShowFields: YES; ID: 5547
C35 = MCD-03431: Capacitor, MLCC,  22pF, X5R, 10 V, 0402, ± 20%, T=0.5mm; Part_Preference: Recommended; Manufacturer: MURATA; Manufacturer_Part_Number: GJM1555C1H220JB01; Order_Code_RS: 172-6870; ShowFields: YES; ID: 5547
C36 = MCD-03431: Capacitor, MLCC,  18pF, X5R, 10 V, 0402, ± 20%, T=0.5mm; Part_Preference: Recommended; Manufacturer: MURATA; Manufacturer_Part_Number: GJM1555C1H180JB01; Order_Code_RS: 172-6870; ShowFields: YES; ID: 5547
C37 = MCD-03431: Part_Preference: Recommended; Manufacturer: MURATA; ShowFields: YES; ID: 5547
C40 = MCD-03431: Capacitor, MLCC,  22pF, X5R, 10 V, 0402, ± 20%, T=0.5mm; Part_Preference: Recommended; Manufacturer: MURATA; Manufacturer_Part_Number: GJM1555C1H220JB01; ShowFields: YES
L11 = MCD-01766: Inductor, 7.5nH, +/-2%, Itemp=460mA max, 0R16, 0402, T= 0.6mm, Qmin=30; Manufacturer_Part_Number: 0603CS-7N5XJL; Manufacturer: Coilcraft
L12 = MCD-01766: Inductor, 2.7nH, +/-2%, Itemp=460mA max, 0R16, 0402, T= 0.6mm, Qmin=30; Manufacturer_Part_Number: LQG15HN2N7S02D; Munufacturer: MURATA
L13 = MCD-01766: Inductor, 27nH, +/-2%, Itemp=460mA max, 0R16, 0402, T= 0.6mm, Qmin=30; Manufacturer_Part_Number: 0603CS-27NXJL; Manufacturer: Coilcraft
L14 = MCD-01766: Inductor, 15nH, +/-2%, Itemp=460mA max, 0R16, 0402, T= 0.6mm, Qmin=30; Manufacturer_Part_Number: LQG15HN15NJ02D; Manufacturer: Murata
L15 = MCD-01766: Inductor, 10nH, +/-2%, Itemp=460mA max, 0R16, 0402, T= 0.6mm, Qmin=30; Manufacturer_Part_Number: 0603CS-10NXJL; Manufacturer: Coilcraft
L16 = MCD-01766: Inductor, 47nH, +/-2%, Itemp=460mA max, 0R16, 0402, T= 0.6mm, Qmin=30; Manufacturer_Part_Number: 0603CS-47NXJL; Manufacturer: Coilcraft
L17 = MCD-01766: Inductor, 4.7nH, +/-2%, Itemp=460mA max, 0R16, 0402, T= 0.6mm, Qmin=30; Manufacturer_Part_Number: LQG15HN4N7S02D; Manufacturer: Murata
L18 = MCD-01766: 0R resistor; Manufacturer_Part_Number: ERJ3GEJ0R0; Manufacturer: Panasonic
L19 = MCD-01766
L20 = MCD-01766: Inductor, 10nH, +/-2%, Itemp=460mA max, 0R16, 0402, T= 0.6mm, Qmin=30; Manufacturer_Part_Number: BLM15BD601SN1; Manufacturer: Murata
L21 = MCD-01766: Inductor, 27nH, +/-2%, Itemp=460mA max, 0R16, 0402, T= 0.6mm, Qmin=30; Manufacturer_Part_Number: LQG15HN27NJ02D; Manufacturer: Murata
U2 = SKY66121-11: 169 to 170 MHz Transmit / Receive Front-End  Module for 27 dBm (no BYPASS funct); Manufacturer: Skyworks

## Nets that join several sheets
GND: MCU_IOs (28 pins), RF (26 pins), Supply (14 pins), FEM (18 pins)
VDD: MCU_IOs (C24.2 CN1.32), RF (C7.2 X2.4), Supply (10 pins)
VDD_FEM: MCU_IOs (CN1.2), FEM (5 pins)
VFBSD: RF (C14.1 C15.2 L8.1), Supply (C22.2 C23.1 L10.1 U1.40)
ANT Path: RF (C2.2 L1.1 R1.1), FEM (C38.2 L18.2)
CSD: MCU_IOs (SB11.2 U1.11), FEM (U2.1)
CTX: MCU_IOs (SB20.1 U1.19), FEM (U2.3)
GPIO5/SWDIO: MCU_IOs (CN1.13 U1.1), Supply (R3.2)
GPIO6/SWCLK: MCU_IOs (CN1.15 U1.2), Supply (R4.2)
GPIO23/VCP1_RX: MCU_IOs (CN1.45 SB14.1), Supply (R7.1)
GPIO24/VCP1_TX: MCU_IOs (CN1.47 SB16.1), Supply (R6.2)
NRST: MCU_IOs (C20.2 CN1.12 U1.36), Supply (R5.2)
RX Path: RF (C10.2 L6.2), FEM (C25.1)
TCXO_EN: MCU_IOs (U1.8), RF (X2.1)
TX Path: RF (C5.1), FEM (C40.2 L21.1)

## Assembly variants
169_27dBm: not fitted C1 C2 C6 C10 C12 C19 C24 C26 C37 C38 CN3 L3 L4 L19 R1 R3 R4 R5 R6 R7 R8 SB2 SB3 SB4 SB6 SB9 SB11 SB17 SB20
